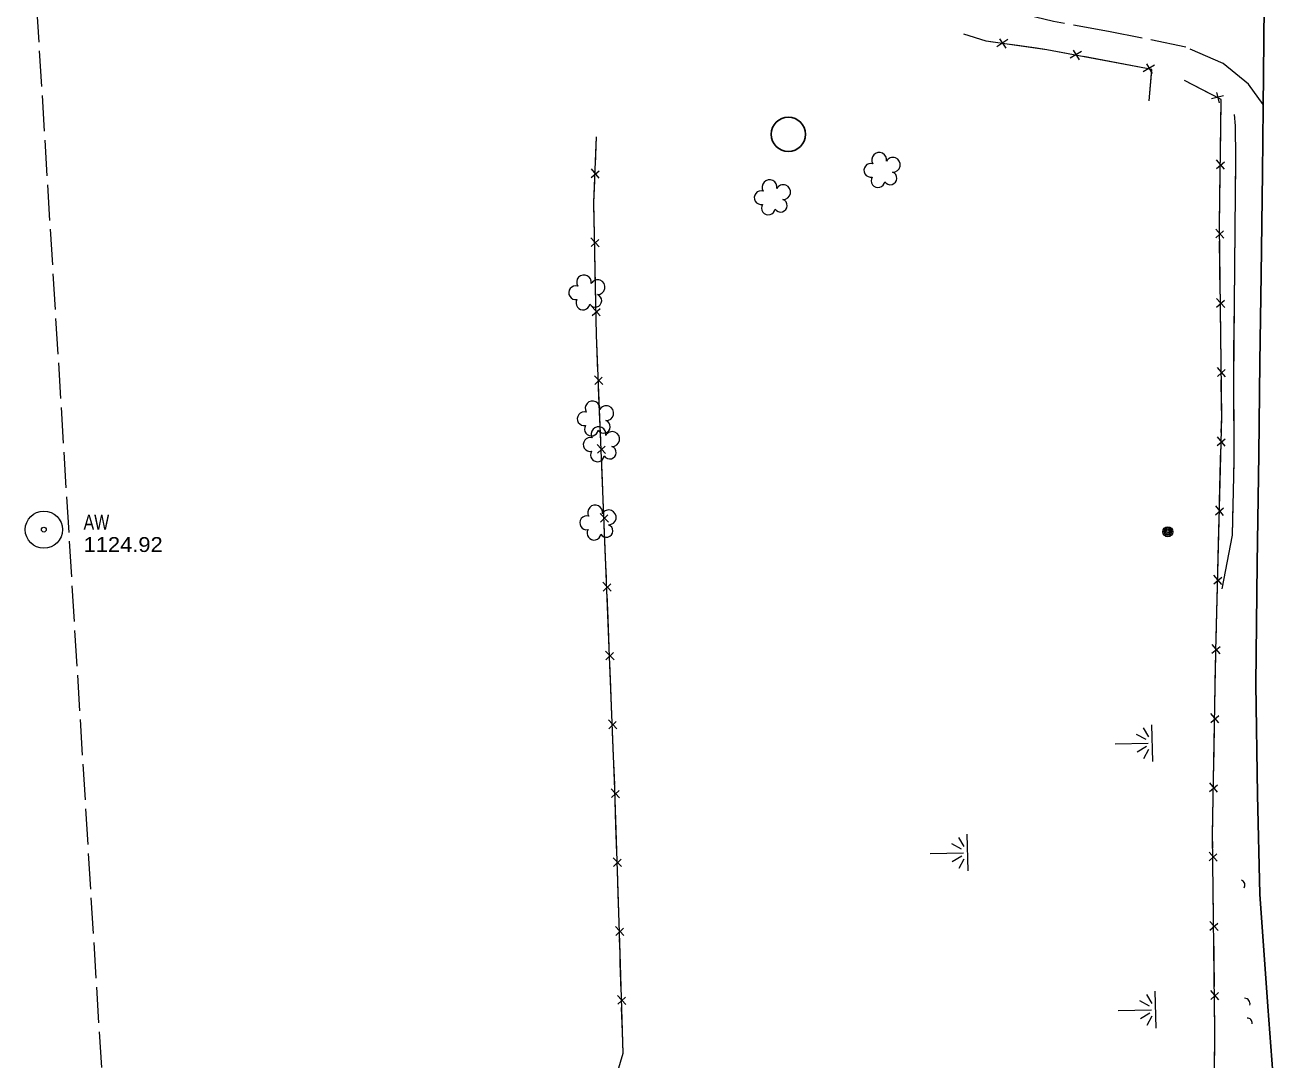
# Model space of a CAD drawing. Extents: x 296527 to 298902, y 45711 to 46924.
# Drawn here: x 297190 to 297699, y 46129 to 46546 of the extents above; entities that cross this region are included whole.
import ezdxf

# ---------------------------------------------------------------- set-up
doc = ezdxf.new("R2010")
doc.units = 0
doc.header["$LTSCALE"] = 2.4
doc.linetypes.add('LONG_DASHED', pattern=[7.5, 6, -1.5])
for name, color, linetype, lineweight in [('11', 7, 'Continuous', 25), ('12', 7, 'Continuous', 13), ('14', 7, 'Continuous', 13), ('15', 7, 'Continuous', 13), ('17', 7, 'LONG_DASHED', 13), ('18', 7, 'Continuous', 13), ('19', 7, 'Continuous', 13), ('4', 7, 'Continuous', 13), ('6', 7, 'Continuous', 13)]:
    doc.layers.add(name, color=color, linetype=linetype, lineweight=lineweight)

msp = doc.modelspace()

# ---------------------------------------------------------------- linework, layer by layer
at = {"layer": '11'}
msp.add_lwpolyline([(297692.464, 45930.163), (297697.156, 45968.357), (297698.514, 45980.054), (297696.031, 46018.05), (297694.427, 46060.322), (297693.685, 46107.184), (297690.534, 46150.067), (297687.278, 46195.408), (297686.38, 46235.432), (297685.597, 46280.048), (297686.183, 46328.589), (297686.8, 46372.646), (297687.26, 46409.842), (297687.847, 46444.997), (297688.271, 46486.097), (297688.584, 46512.367), (297689.185, 46567.008), (297689.042, 46613.28), (297688.816, 46663.597), (297687.713, 46712.034), (297687.351, 46767.843), (297688.042, 46821.878), (297688.175, 46864.957), (297687.551, 46914.245)], dxfattribs=at)
at = {"layer": '12', "lineweight": 25}
msp.add_circle((297497.254, 46501.618), 6.931, dxfattribs=at)
at = {"layer": '14'}
for centre, radius in [((297650.19, 46341.456), 2.018), ((297650.177, 46341.453), 1.518), ((297650.217, 46341.46), 1.008), ((297650.207, 46341.464), 0.502)]:
    msp.add_circle(centre, radius, dxfattribs=at)
at = {"layer": '15'}
for p, q in [((297585.712, 46539.783), (297581.278, 46536.878)), ((297585.056, 46536.358), (297582.543, 46540.146)), ((297597.299, 46536.299), (297586.693, 46537.76)), ((297615.369, 46535.006), (297610.797, 46532.324)), ((297614.544, 46531.617), (297612.222, 46535.525)), ((297626.769, 46530.953), (297616.248, 46532.937)), ((297638.731, 46528.697), (297626.769, 46530.953)), ((297644.806, 46529.454), (297640.234, 46526.773)), ((297643.981, 46526.066), (297641.659, 46529.974)), ((297642.717, 46515.141), (297643.613, 46525.81)), ((297666.983, 46518.068), (297656.944, 46523.338)), ((297672.601, 46517.086), (297667.797, 46515.944)), ((297670.943, 46514.293), (297669.939, 46518.407)), ((297671.533, 46504.354), (297671.678, 46514.325)), ((297671.368, 46493.017), (297671.533, 46504.354)), ((297419.495, 46489.394), (297419.946, 46500.671)), ((297673.03, 46487.562), (297669.841, 46491.331)), ((297417.792, 46484.222), (297421.062, 46486.881)), ((297421.011, 46483.923), (297417.933, 46487.755)), ((297669.789, 46487.779), (297673.005, 46490.533)), ((297671.126, 46476.454), (297671.271, 46486.425)), ((297670.961, 46465.117), (297671.126, 46476.454)), ((297419.114, 46461.633), (297418.906, 46472.918)), ((297672.76, 46459.708), (297669.471, 46463.391)), ((297669.514, 46459.839), (297672.656, 46462.677)), ((297420.948, 46456.261), (297417.651, 46459.906)), ((297417.716, 46456.371), (297420.825, 46459.216)), ((297671.154, 46448.553), (297671.033, 46458.525)), ((297419.419, 46445.148), (297419.236, 46455.073)), ((297419.627, 46433.864), (297419.419, 46445.148)), ((297671.292, 46437.216), (297671.154, 46448.553)), ((297673.1, 46431.807), (297669.811, 46435.49)), ((297421.46, 46428.491), (297418.163, 46432.136)), ((297418.229, 46428.601), (297421.338, 46431.446)), ((297669.854, 46431.938), (297672.996, 46434.777)), ((297671.494, 46420.652), (297671.372, 46430.624)), ((297671.632, 46409.315), (297671.494, 46420.652)), ((297420.476, 46406.104), (297420.008, 46417.38)), ((297422.432, 46400.775), (297419.052, 46404.343)), ((297673.44, 46403.906), (297670.151, 46407.589)), ((297670.194, 46404.037), (297673.336, 46406.876)), ((297419.199, 46400.81), (297422.242, 46403.726)), ((297421.159, 46389.63), (297420.748, 46399.548)), ((297671.834, 46392.751), (297671.712, 46402.723)), ((297421.627, 46378.353), (297421.159, 46389.63)), ((297670.098, 46376.195), (297673.343, 46378.914)), ((297673.336, 46375.943), (297670.187, 46379.746)), ((297423.583, 46373.024), (297420.203, 46376.593)), ((297420.35, 46373.06), (297423.393, 46375.976)), ((297671.314, 46364.856), (297671.566, 46374.825)), ((297422.31, 46361.879), (297421.899, 46371.797)), ((297671.028, 46353.521), (297671.314, 46364.856)), ((297422.778, 46350.602), (297422.31, 46361.879)), ((297424.734, 46345.273), (297421.354, 46348.842)), ((297669.393, 46348.301), (297672.639, 46351.02)), ((297672.632, 46348.049), (297669.483, 46351.852)), ((297421.501, 46345.309), (297424.544, 46348.225)), ((297423.461, 46334.128), (297423.05, 46344.046)), ((297670.609, 46336.962), (297670.861, 46346.931)), ((297670.323, 46325.627), (297670.609, 46336.962)), ((297668.688, 46320.406), (297671.934, 46323.126)), ((297671.927, 46320.154), (297668.778, 46323.958)), ((297425.869, 46317.519), (297422.494, 46321.093)), ((297422.635, 46317.56), (297425.683, 46320.471)), ((297669.905, 46309.068), (297670.157, 46319.037)), ((297424.579, 46306.376), (297424.183, 46316.295)), ((297669.619, 46297.733), (297669.905, 46309.068)), ((297425.029, 46295.099), (297424.579, 46306.376)), ((297426.977, 46289.767), (297423.603, 46293.341)), ((297423.744, 46289.807), (297426.791, 46292.719)), ((297667.984, 46292.512), (297671.23, 46295.232)), ((297671.223, 46292.26), (297668.074, 46296.064)), ((297425.687, 46278.623), (297425.291, 46288.542)), ((297669.294, 46281.172), (297669.47, 46291.142)), ((297426.137, 46267.346), (297425.687, 46278.623)), ((297669.094, 46269.835), (297669.294, 46281.172)), ((297667.499, 46264.602), (297670.724, 46267.346)), ((297670.74, 46264.375), (297667.562, 46268.154)), ((297428.085, 46262.014), (297424.711, 46265.588)), ((297424.852, 46262.055), (297427.899, 46264.966)), ((297668.802, 46253.273), (297668.978, 46263.244)), ((297426.795, 46250.871), (297426.399, 46260.79)), ((297668.602, 46241.936), (297668.802, 46253.273)), ((297427.245, 46239.594), (297426.795, 46250.871)), ((297429.163, 46234.246), (297425.82, 46237.848)), ((297425.931, 46234.314), (297429.003, 46237.199)), ((297667.007, 46236.703), (297670.232, 46239.447)), ((297670.247, 46236.476), (297667.069, 46240.255)), ((297427.778, 46223.114), (297427.467, 46233.036)), ((297668.309, 46225.374), (297668.485, 46235.345)), ((297428.132, 46211.833), (297427.778, 46223.114)), ((297670.079, 46208.628), (297666.789, 46212.311)), ((297666.833, 46208.759), (297669.974, 46211.598)), ((297430.034, 46206.485), (297426.69, 46210.087)), ((297426.801, 46206.553), (297429.874, 46209.438)), ((297668.475, 46197.474), (297668.352, 46207.445)), ((297428.649, 46195.353), (297428.338, 46205.275)), ((297668.615, 46186.136), (297668.475, 46197.474)), ((297429.003, 46184.072), (297428.649, 46195.353)), ((297430.905, 46178.724), (297427.561, 46182.327)), ((297427.672, 46178.792), (297430.744, 46181.677)), ((297670.423, 46180.728), (297667.134, 46184.41)), ((297667.177, 46180.858), (297670.319, 46183.697)), ((297668.819, 46169.573), (297668.696, 46179.544)), ((297429.858, 46156.311), (297429.516, 46167.592)), ((297668.959, 46158.235), (297668.819, 46169.573)), ((297670.768, 46152.827), (297667.478, 46156.509)), ((297667.522, 46152.957), (297670.663, 46155.796)), ((297431.755, 46150.961), (297428.415, 46154.567)), ((297428.522, 46151.032), (297431.597, 46153.914)), ((297669.163, 46141.672), (297669.04, 46151.643)), ((297430.358, 46139.83), (297430.057, 46149.752))]:
    msp.add_line(p, q, dxfattribs=at)
for points in [[(297642.717, 46515.141), (297643.776, 46527.746), (297601.453, 46535.727), (297576.947, 46539.103), (297567.984, 46541.976)], [(297579.682, 46538.726), (297576.947, 46539.103), (297567.984, 46541.976)], [(297609.294, 46534.248), (297601.453, 46535.727), (297597.299, 46536.299)], [(297231.975, 45937.535), (297237.679, 45937.392), (297316.078, 45934.559), (297398.392, 45934.381), (297521.626, 45935.253), (297609.523, 45938.083), (297665.677, 45942.947), (297668.427, 46057.646), (297669.182, 46140.171), (297668.204, 46219.412), (297669.512, 46293.511), (297671.894, 46387.823), (297670.956, 46464.804), (297671.697, 46515.594), (297656.944, 46523.338)], [(297228.598, 45992.845), (297255.591, 45993.205), (297273.582, 45993.508), (297289.114, 45998.857), (297381.272, 46075.405), (297426.761, 46118.188), (297430.618, 46131.261), (297429.398, 46171.469), (297427.319, 46237.747), (297423.718, 46327.93), (297419.87, 46420.715), (297418.884, 46474.114), (297419.946, 46500.671)], [(297418.906, 46472.918), (297418.884, 46474.114), (297419.233, 46482.837)], [(297420.008, 46417.38), (297419.87, 46420.715), (297419.748, 46427.303)], [(297671.732, 46381.415), (297671.894, 46387.823), (297671.834, 46392.751)], [(297423.921, 46322.851), (297423.718, 46327.93), (297423.461, 46334.128)], [(297668.27, 46214.037), (297668.204, 46219.412), (297668.309, 46225.374)], [(297429.516, 46167.592), (297429.398, 46171.469), (297429.208, 46177.514)], [(297429.85, 46128.659), (297430.618, 46131.261), (297430.358, 46139.83)], [(297669.092, 46130.334), (297669.182, 46140.171), (297669.163, 46141.672)]]:
    msp.add_lwpolyline(points, dxfattribs=at)
for centre, radius, start, end in [((297679.274, 46199.091), 2.014, 325.22439, 71.46396), ((297681.147, 46151.242), 2.165, 344.36129, 90.60086), ((297682.247, 46143.565), 1.91, 348.09711, 94.33667)]:
    msp.add_arc(centre, radius, start, end, dxfattribs=at)
at = {"layer": '17'}
msp.add_lwpolyline([(297688.597, 46513.58), (297682.72, 46521.77), (297672.439, 46530.224), (297657.436, 46536.781), (297626.307, 46543.076), (297604.151, 46547.075), (297581.792, 46552.565), (297558.17, 46560.59), (297535.85, 46572.095), (297524.577, 46579.691), (297517.014, 46581.225), (297508.174, 46579.446), (297497.182, 46575.442), (297489.816, 46571.477), (297478.71, 46562.147), (297471.422, 46556.804), (297461.859, 46552.581), (297452.337, 46551.488), (297443.844, 46552.291), (297437.568, 46552.903)], dxfattribs=at)
at = {"layer": '18'}
for centre, radius, start, end in [((297533.846, 46491.308), 2.974, 349.94487, 211.17875), ((297539.362, 46489.348), 2.975, 267.59569, 150.56896), ((297530.486, 46487.114), 2.777, 72.91576, 280.68875), ((297538.355, 46483.918), 2.611, 212.30092, 70.23353), ((297489.642, 46480.302), 2.974, 349.94487, 211.17875), ((297495.158, 46478.342), 2.975, 267.59569, 150.56896), ((297533.402, 46482.977), 2.783, 149.59278, 350.60382), ((297486.282, 46476.108), 2.777, 72.91576, 280.68875), ((297489.198, 46471.971), 2.783, 149.59278, 350.60382), ((297494.151, 46472.912), 2.611, 212.30092, 70.23353), ((297411.534, 46437.78), 2.777, 72.91576, 280.68875), ((297414.894, 46441.974), 2.974, 349.94487, 211.17875), ((297420.41, 46440.014), 2.975, 267.59569, 150.56896), ((297414.45, 46433.643), 2.783, 149.59278, 350.60382), ((297419.403, 46434.584), 2.611, 212.30092, 70.23353), ((297418.327, 46391.172), 2.974, 349.94487, 211.17875), ((297414.967, 46386.978), 2.777, 72.91576, 280.68875), ((297423.843, 46389.212), 2.975, 267.59569, 150.56896), ((297417.883, 46382.841), 2.783, 149.59278, 350.60382), ((297422.836, 46383.782), 2.611, 212.30092, 70.23353), ((297417.383, 46376.587), 2.777, 72.91576, 280.68875), ((297420.743, 46380.781), 2.974, 349.94487, 211.17875), ((297426.259, 46378.821), 2.975, 267.59569, 150.56896), ((297420.299, 46372.45), 2.783, 149.59278, 350.60382), ((297425.252, 46373.391), 2.611, 212.30092, 70.23353), ((297419.363, 46349.228), 2.974, 349.94487, 211.17875), ((297424.879, 46347.268), 2.975, 267.59569, 150.56896), ((297416.003, 46345.034), 2.777, 72.91576, 280.68875), ((297423.872, 46341.838), 2.611, 212.30092, 70.23353), ((297418.919, 46340.897), 2.783, 149.59278, 350.60382)]:
    msp.add_arc(centre, radius, start, end, dxfattribs=at)
at = {"layer": '19'}
for p, q in [((297677.351, 46467.794), (297677.369, 46470.189)), ((297677.29, 46460.608), (297677.314, 46463.003)), ((297677.219, 46453.423), (297677.243, 46455.818)), ((297676.899, 46371.965), (297676.886, 46374.361)), ((297676.792, 46364.777), (297676.849, 46367.173)), ((297676.619, 46357.59), (297676.677, 46359.986)), ((297640.233, 46262.438), (297642.416, 46258.808)), ((297644.154, 46248.894), (297643.778, 46263.684)), ((297641.51, 46257.684), (297637.605, 46259.786)), ((297628.9, 46255.934), (297642.316, 46256.274)), ((297641.581, 46254.88), (297637.788, 46252.583)), ((297640.548, 46250.067), (297642.543, 46253.804)), ((297565.754, 46218.268), (297567.937, 46214.638)), ((297569.675, 46204.724), (297569.299, 46219.514)), ((297554.421, 46211.764), (297567.837, 46212.104)), ((297567.031, 46213.514), (297563.126, 46215.616)), ((297567.102, 46210.71), (297563.309, 46208.413)), ((297566.069, 46205.897), (297568.064, 46209.634)), ((297641.56, 46154.98), (297643.743, 46151.35)), ((297645.481, 46141.436), (297645.105, 46156.226)), ((297642.837, 46150.226), (297638.932, 46152.328)), ((297630.227, 46148.476), (297643.643, 46148.816)), ((297642.908, 46147.422), (297639.115, 46145.125)), ((297641.875, 46142.609), (297643.87, 46146.346))]:
    msp.add_line(p, q, dxfattribs=at)
for points in [[(297672.067, 46318.446), (297676.2, 46340.112), (297676.912, 46369.785), (297676.724, 46402.418), (297677.019, 46433.136), (297677.317, 46463.321), (297677.533, 46492.074), (297677.44, 46505.102), (297677.022, 46509.667)], [(297677.405, 46474.979), (297677.533, 46492.074), (297677.44, 46505.102), (297677.022, 46509.667)], [(297676.834, 46413.897), (297677.019, 46433.136), (297677.172, 46448.632)], [(297676.858, 46379.153), (297676.724, 46402.418), (297676.834, 46413.897)], [(297672.067, 46318.446), (297676.2, 46340.112), (297676.504, 46352.799)]]:
    msp.add_lwpolyline(points, dxfattribs=at)
at = {"layer": '4', "linetype": 'LONG_DASHED'}
msp.add_lwpolyline([(297236.947, 45856.087), (297194.081, 46558.227), (297396.47, 46901.483)], dxfattribs=at)
at = {"layer": '6'}
for radius in [7.5, 0.96]:
    msp.add_circle((297197.195, 46342.295), radius, dxfattribs=at)

# ---------------------------------------------------------------- texts
for s, width, p in [('AW', 0.8, (297213.195, 46342.295)), ('1124.92', 1.1, (297213.195, 46333.295))]:
    msp.add_text(s, height=6, dxfattribs=dict(at, width=width)).set_placement(p)

doc.saveas('drawing.dxf')
